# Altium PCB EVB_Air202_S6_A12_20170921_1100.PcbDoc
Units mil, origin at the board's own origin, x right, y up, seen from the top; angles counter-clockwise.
Board outline 964.57 x 1338.58 mil, 2 copper layers (Top, Bottom), stack 12.7 mil thick; 57 components, 47 nets, 194 pads, 152 vias.
Unrouted connection lines stored in the file: 113.
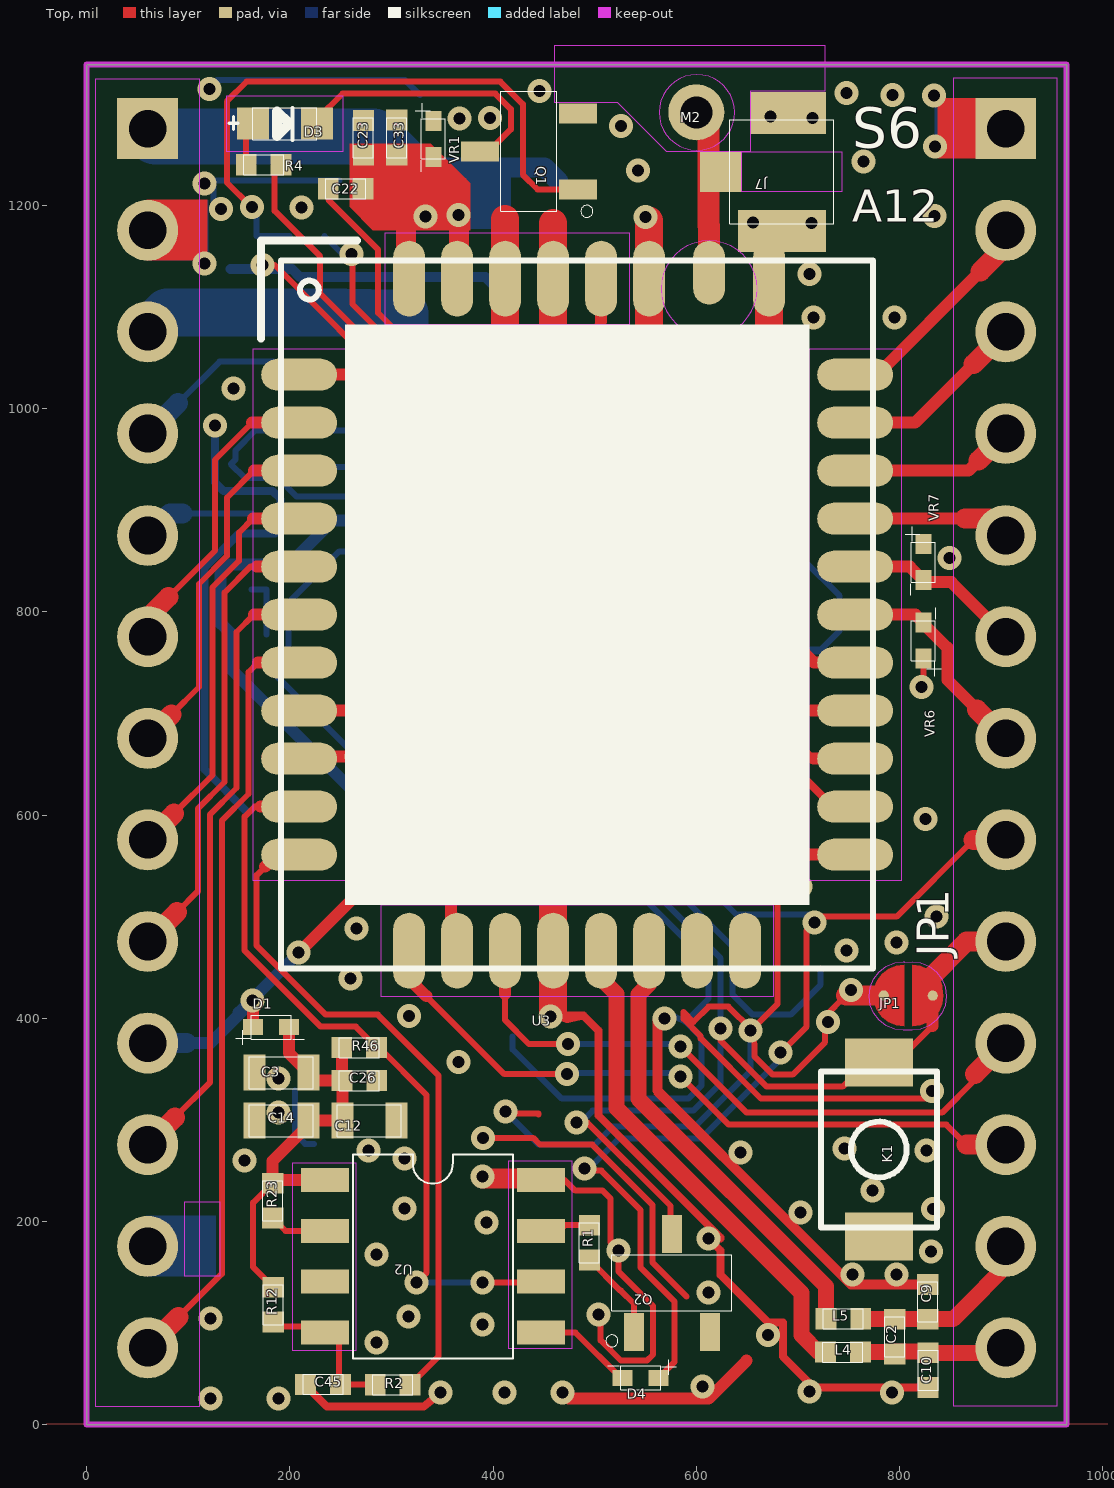
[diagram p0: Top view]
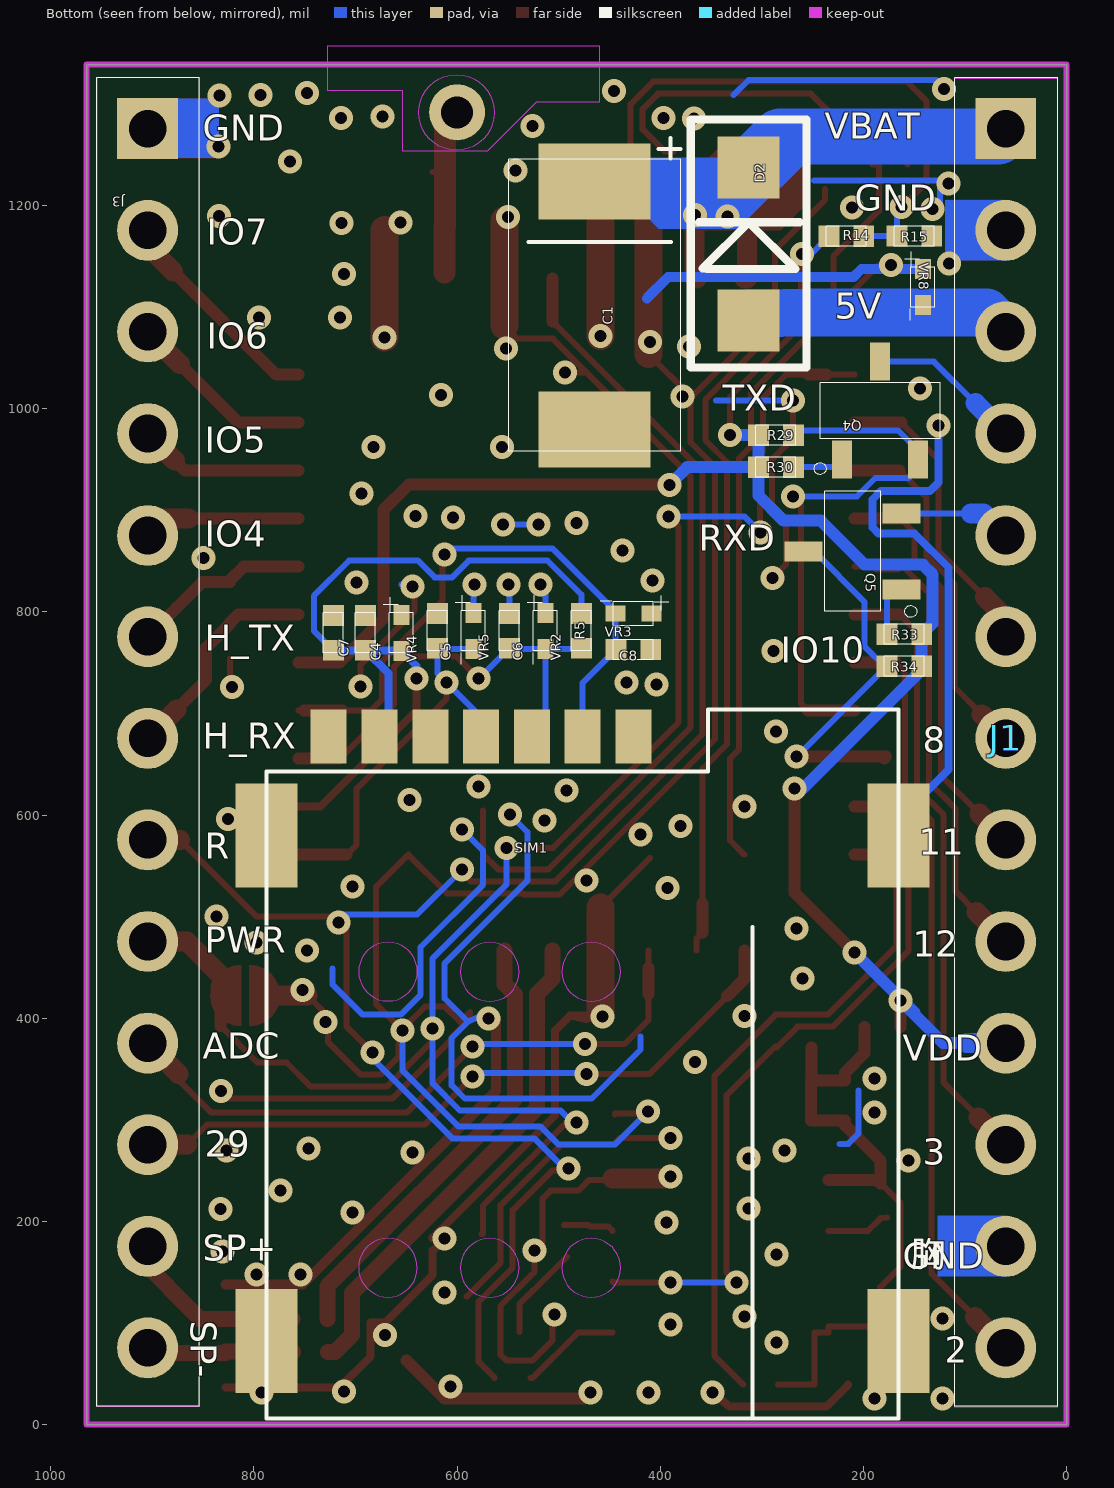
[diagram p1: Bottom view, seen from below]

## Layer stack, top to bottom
Solder Mask Top: solder mask 0.4, Solder Resist, Dk 3.5
Top: signal copper 1.35
Dielectric 1: dielectric 10, FR-4, Dk 4.3
Bottom: signal copper 1.35
Solder Mask Bottom: solder mask 0.4, Solder Resist, Dk 3.5

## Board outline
0,1338.58 964.57,1338.58 964.57,0 0,0

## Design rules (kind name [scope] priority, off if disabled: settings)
Clearance "Clearance - Default - DEFAULT- SMD" [IsVia vs IsSMTPin] p1: gap=5.91 ignorepadtopadclearanceinfootprint=FALSE
Clearance "Clearance - Default - DEFAULT - Via" [IsVia vs IsVia] p2: gap=5.91 ignorepadtopadclearanceinfootprint=FALSE
Clearance "Clearance - Default - DEFAULT - Net" [All] p3: gap=5.91 ignorepadtopadclearanceinfootprint=FALSE except(0: Arc-Hole Track-Hole SMDPad-Hole THPad-Hole Via-Hole Fill-Hole Poly-Hole Region-Hole Text-Hole; 10: Text-Text)
ComponentClearance "ComponentClearance - Default - DEFAULT" [All] p1: gap=6 collisioncheckmode=3 verticalgap=10 showdistances=FALSE
FanoutControl Fanout_LCC [IsLCC] p1: bgadir=Out bgaviamode=Centered fanoutstyle=Auto fanoutdirection=Alternating viagrid=1 // Fanout_LCC (Default Rule)
FanoutControl Fanout_BGA [IsBGA] p2: bgadir=Out bgaviamode=Centered fanoutstyle=Auto fanoutdirection=Alternating viagrid=1 // Fanout_BGA (Default Rule)
FanoutControl Fanout_Small [(CompPinCount < 5)] p3: bgadir=Out bgaviamode=Centered fanoutstyle=Auto fanoutdirection=OutThenIn viagrid=1 // Fanout_Small (Default Rule)
FanoutControl Fanout_SOIC [IsSOIC] p4: bgadir=Out bgaviamode=Centered fanoutstyle=Auto fanoutdirection=Alternating viagrid=1 // Fanout_SOIC (Default Rule)
HoleToHoleClearance "HoleToHoleClearance - Default - DEFAULT" [All] p1: gap=6 allowstackedmicrovias=TRUE
MaxMinImpedance "Default Impedance" [All] p1: minimum=50.00 maximum=150.0
ParallelSegment "Default Parallel Segment Same Layer" [All] p1: limit=1000 gap=200
ParallelSegment "Default Parallel Segment Adjasent" [All] p2: limit=1000 gap=200
PlaneConnect "Default PlaneConnect" [All] p1: planeconnectstyle=Relief reliefexpansion=20 reliefentries=0 reliefconductorwidth=15 reliefairgap=10
PolygonConnect "PolygonConnect - Default SMT" [IsSMTPin] p1: connectstyle=Direct reliefconductorwidth=11.81 reliefentries=4 polygonreliefangle="45 Angle" airgapwidth=10
PolygonConnect "PolygonConnect - Default Pad" [All] p2: connectstyle=Direct reliefconductorwidth=15 reliefentries=4 polygonreliefangle="45 Angle" airgapwidth=10
RoutingLayers "RoutingLayers - Default - DEFAULT" [All] p1: top layer_v5=TRUE bottom layer_v5=TRUE
RoutingPriority "RoutingPriority - Default - DEFAULT" [All] p1: routingpriority=3
RoutingTopology "Default Routing Topology" [All] p1: topology=Shortest
RoutingVias "RoutingVias - Default - DEFAULT" [All] p1: holewidth=11.81 width=23.62 viastyle="Through Hole" minholewidth=11.81 minwidth=23.62 maxholewidth=11.81 maxwidth=23.62
SMDToCorner "SMDToCorner - Default - DEFAULT" [All] p1: distance=59055
SolderMaskExpansion [All] p1: expansion=4
Width "Default Width" [All] p1: maxlimit=78.74 minlimit=5.91 preferedwidth=5.91
20 further rules are at their usual default settings.

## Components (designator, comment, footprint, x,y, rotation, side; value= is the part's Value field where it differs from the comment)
C1 "CASEN" CASEN 464.58,1101.65 r270 bottom
C2 "SC0402" SC0402 795.32,86.66 r90 top
C3 "SC0603" SC0603 191.58,346.63 r0 top
C4 "SC0402" SC0402 690.22,779.32 r270 bottom
C5 "SC0402" SC0402 619.35,781.29 r270 bottom
C6 "SC0402" SC0402 548.49,781.29 r270 bottom
C7 "SC0402" SC0402 721.72,779.32 r270 bottom
C8 "SC0402" SC0402 426.63,762.98 r0 bottom
C9 "SC0402" SC0402 827.77,121 r90 top
C10 "SC0402" SC0402 828.04,53.68 r270 top
C12 "SC0603" SC0603 278.2,299.39 r180 top
C14 "SC0603" SC0603 191.58,299.39 r0 top
C22 "SC0402" SC0402 254.91,1216.49 r180 top
C23 "SC0402" SC0402 272.3,1266.58 r90 top
C26 "SC0402" SC0402 268.35,338.76 r0 top
C33 "SC0402" SC0402 305.12,1266.91 r90 top
C45 "SC0402" SC0402 232.57,39.61 r0 top
D1 "ESD-TVS-UM5079" ESD-TVS-UM5079 181.4,391.44 r180 top
D2 "DO-214AC" DO-214AC 313,1237.48 r90 bottom
D3 "LED-0603" LED-0603 194.99,1280.54 r0 top
D4 "ESD-TVS-UM5079" ESD-TVS-UM5079 545.29,46.06 r0 top
J1 "DIP13X1-2.54" DIP13X1-2.54 60,1275.59 r270 bottom
J3 "DIP13X1-2.54" DIP13X1-2.54 904.57,1275.59 r270 bottom
J7 "RF-ANT-SOCKET-U.FL-R-SMT" RF-ANT-SOCKET-U.FL-R-SMT 684.25,1233.02 r270 top
JP1 "R60L08" R60L08 812.7,392.32 r0 top
K1 "KEY-2PIN" KEY-2PIN 779.64,270.87 r90 top
L4 "SL0402" SL0402 744.35,71.45 r180 top
L5 "SL0402" SL0402 744.76,104.24 r180 top
M2 "HOLE-0.9MM" HOLE-0.9MM 599.93,1291.77 r0 top
Q1 "SOT-23(MMBT3904)" SOT-23(MMBT3904) 435.16,1253.38 r0 top
Q2 "SOT-23(MMBT3904)" SOT-23(MMBT3904) 576.02,139.58 r270 top
Q4 "SOT-23(MMBT3904)" SOT-23(MMBT3904) 183.62,998.17 r270 bottom
Q5 "SOT-23(MMBT3904)" SOT-23(MMBT3904) 210.64,859.53 r180 bottom
R1 "SR0402" SR0402 494.86,179.23 r270 top
R2 "SR0402" SR0402 301.18,39.37 r180 top
R4 "SR0402" SR0402 174.06,1240.2 r0 top
R5 "SR0402" SR0402 477.62,781.29 r90 bottom
R12 "SR0402" SR0402 183.54,118.2 r270 top
R14 "SR0402" SR0402 216.93,1169.79 r180 bottom
R15 "SR0402" SR0402 149.97,1169.93 r0 bottom
R23 "SR0402" SR0402 183.07,220.47 r90 top
R29 "SR0402" SR0402 286.17,973.96 r0 bottom
R30 "SR0402" SR0402 286.17,942.47 r0 bottom
R33 "SR0402" SR0402 159.88,777.97 r180 bottom
R34 "SR0402" SR0402 159.88,746.48 r180 bottom
R46 "SR0402" SR0402 268.17,371.24 r0 top
SIM1 "5100106-X1101S-X-A" 5100106-X1101S-X-A 726.38,677.17 r180 bottom
U2 "EM78P153B-SOP8" EM78P153B-SOP8 340.62,165.81 r270 top
U3 "A6391_A11" A6391_A11 191.34,448.82 r0 top
VR1 "ESD-TVS-UM5079" ESD-TVS-UM5079 341.27,1265.66 r90 top
VR2 "ESD-TVS-UM5079" ESD-TVS-UM5079 513.06,781.29 r90 bottom
VR3 "ESD-TVS-UM5079" ESD-TVS-UM5079 426.63,798.41 r180 bottom
VR4 "ESD-TVS-UM5079" ESD-TVS-UM5079 654.79,779.32 r90 bottom
VR5 "ESD-TVS-UM5079" ESD-TVS-UM5079 583.92,781.29 r90 bottom
VR6 "ESD-TVS-UM5079" ESD-TVS-UM5079 823.5,771.72 r270 top
VR7 "ESD-TVS-UM5079" ESD-TVS-UM5079 823.49,848.9 r90 top
VR8 "ESD-TVS-UM5079" ESD-TVS-UM5079 141.68,1119.73 r90 bottom

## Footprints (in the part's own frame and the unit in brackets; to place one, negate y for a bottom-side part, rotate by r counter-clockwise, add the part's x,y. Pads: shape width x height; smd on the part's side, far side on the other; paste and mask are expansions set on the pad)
5100106-X1101S-X-A [mm]
  rect 0.9x1.35 smd: 1(0,0) 2(1.27,0) 3(2.54,0) 4(3.81,0) 5(5.08,0) 6(6.35,0) 7(7.62,0)
  rect 1.55x2.6 smd: 8(-1.55,-2.475) 9(14.25,-2.475) 10(-1.55,-15.105) 11(14.25,-15.105)
  Top keep-out region: 7.297,-13.277 7.241,-12.995 7.082,-12.757 6.844,-12.598 6.562,-12.542 6.562,-12.542 6.281,-12.598 6.043,-12.757 5.883,-12.995 5.827,-13.277 5.827,-13.277 5.883,-13.558 6.043,-13.796 6.281,-13.956 6.562,-14.012 6.562,-14.012 6.844,-13.956 7.082,-13.796 7.241,-13.558 7.297,-13.277
  Top keep-out region: 4.759,-13.279 4.703,-12.998 4.544,-12.76 4.306,-12.6 4.024,-12.544 4.024,-12.544 3.743,-12.6 3.505,-12.76 3.345,-12.998 3.289,-13.279 3.289,-13.279 3.345,-13.561 3.505,-13.799 3.743,-13.958 4.024,-14.014 4.024,-14.014 4.306,-13.958 4.544,-13.799 4.703,-13.561 4.759,-13.279
  Top keep-out region: 2.215,-13.274 2.159,-12.993 2,-12.754 1.762,-12.595 1.48,-12.539 1.48,-12.539 1.199,-12.595 0.961,-12.754 0.801,-12.993 0.745,-13.274 0.745,-13.274 0.801,-13.555 0.961,-13.794 1.199,-13.953 1.48,-14.009 1.48,-14.009 1.762,-13.953 2,-13.794 2.159,-13.555 2.215,-13.274
  Top keep-out region: 7.299,-5.875 7.243,-5.593 7.083,-5.355 6.845,-5.196 6.564,-5.14 6.564,-5.14 6.282,-5.196 6.044,-5.355 5.885,-5.593 5.829,-5.875 5.829,-5.875 5.885,-6.156 6.044,-6.394 6.282,-6.554 6.564,-6.61 6.564,-6.61 6.845,-6.554 7.083,-6.394 7.243,-6.156 7.299,-5.875
  Top keep-out region: 4.761,-5.877 4.705,-5.596 4.545,-5.358 4.307,-5.198 4.026,-5.142 4.026,-5.142 3.744,-5.198 3.506,-5.358 3.347,-5.596 3.291,-5.877 3.291,-5.877 3.347,-6.159 3.506,-6.397 3.744,-6.556 4.026,-6.612 4.026,-6.612 4.307,-6.556 4.545,-6.397 4.705,-6.159 4.761,-5.877
  Top keep-out region: 2.217,-5.872 2.161,-5.591 2.001,-5.352 1.763,-5.193 1.482,-5.137 1.482,-5.137 1.2,-5.193 0.962,-5.352 0.803,-5.591 0.747,-5.872 0.747,-5.872 0.803,-6.153 0.962,-6.392 1.2,-6.551 1.482,-6.607 1.482,-6.607 1.763,-6.551 2.001,-6.392 2.161,-6.153 2.217,-5.872
  silkscreen extent -1.55,-17.04 14.25,0.68
A6391_A11 [mm]
  oval 1.9x0.8 smd: 1(0.45,14.85) 2(0.45,13.65) 3(0.45,12.45) 4(0.45,11.25) 5(0.45,10.05) 6(0.45,8.85) 7(0.45,7.65) 8(0.45,6.45) 9(0.45,5.25) 10(0.45,4.05) 11(0.45,2.85) 20(14.35,2.85) 21(14.35,4.05) 22(14.35,5.25) 23(14.35,6.45) 24(14.35,7.65) 25(14.35,8.85) 26(14.35,10.05) 27(14.35,11.25) 28(14.35,12.45) 29(14.35,13.65) 30(14.35,14.85)
  oval 0.8x1.9 smd: 12(3.2,0.45) 13(4.4,0.45) 14(5.6,0.45) 15(6.8,0.45) 16(8,0.45) 17(9.2,0.45) 18(10.4,0.45) 19(11.6,0.45) 31(12.2,17.25) 33(9.2,17.25) 34(8,17.25) 35(6.8,17.25) 36(5.6,17.25) 37(4.4,17.25) 38(3.2,17.25)
  oval 0.8x1.6 smd: 32(10.7,17.4)
  rect 1.5x1.5 smd: 39(3.2,2.85) 40(11.6,2.85) 41(7.4,7.35)
  Top keep-out region: 2.6,18.4 8.7,18.4 8.7,16.1 2.6,16.1 2.6,18.4
  Top keep-out region: -0.7,15.5 1.6,15.5 1.6,2.2 -0.7,2.2 -0.7,15.5
  Top keep-out region: 2.5,1.6 12.3,1.6 12.3,-0.7 2.5,-0.7 2.5,1.6
  Top keep-out region: 13.2,15.5 15.5,15.5 15.5,2.2 13.2,2.2 13.2,15.5
  Top keep-out region: 11.9,17 11.809,17.459 11.549,17.849 11.159,18.109 10.7,18.2 10.7,18.2 10.241,18.109 9.851,17.849 9.591,17.459 9.5,17 9.5,17 9.591,16.541 9.851,16.151 10.241,15.891 10.7,15.8 10.7,15.8 11.159,15.891 11.549,16.151 11.809,16.541 11.9,17
  silkscreen extent -0.5,0 14.8,18.2
CASEN [mm]
  rect 1.9x2.8 smd: 1(-3.1,0) 2(3.1,0)
  silkscreen extent -4.18,-2.15 3.65,2.15
DIP13X1-2.54 [mil]
  rect 60x60 hole 37: 1(0,0)
  round 60 hole 37: 2(100,0) 3(200,0) 4(300,0) 5(400.39,0) 6(500,0) 7(600,0) 8(700,0) 9(800,0) 10(900,0) 11(1000,0) 12(1100,0) 13(1200,0)
  silkscreen extent -50,-50 1257,51
DO-214AC [mm]
  rrect0% 1.55x1.55 smd: 1(0,0) 2(-3.83,0)
  silkscreen extent -5,-1.45 1.2,1.45
EM78P153B-SOP8 [mm]
  rect 0.6x1.2 smd: 1(-1.905,-2.7) 2(-0.635,-2.7) 3(0.635,-2.7) 4(1.905,-2.7) 5(1.905,2.7) 6(0.635,2.7) 7(-0.635,2.7) 8(-1.905,2.7)
  silkscreen extent -2.55,-2 2.55,2
ESD-TVS-UM5079 [mm]
  rect 0.5x0.4 smd: 1(-0.45,0) 2(0.45,0)
  silkscreen extent -0.83,-0.3 0.89,0.45
HOLE-0.9MM [mm]
  round 1.4 hole 0.8: 1(0,0)
KEY-2PIN [mm]
  rect 1.2x1.7 smd: 1(-2.175,0) 2(2.175,0)
  silkscreen extent -1.95,-1.45 1.95,1.45
LED-0603 [mm]
  rect 0.8x0.8 smd: 1(-0.8,0) 2(0.8,0)
  Top keep-out region: -1.45,0.7 1.45,0.7 1.45,-0.7 -1.45,-0.7 -1.45,0.7
  silkscreen extent -1.39,-0.41 0.8,0.4
R60L08 [mil]
  round 10 smd: 1(-28.22,30.19) 2(20,30)
  Top region: -8.22,-0.07 -16.05,0.96 -23.35,3.98 -29.62,8.79 -34.42,15.06 -37.45,22.36 -38.48,30.19 -37.45,38.02 -34.42,45.32 -29.62,51.59 -23.35,56.39 -16.05,59.42 -8.22,60.45 -8.22,60.19 -8.22,0.19
  Top region: 0,60.26 7.83,59.23 15.13,56.2 21.4,51.4 26.2,45.13 29.23,37.83 30.26,30 29.23,22.17 26.2,14.87 21.4,8.6 15.13,3.8 7.83,0.77 0,-0.26 0,0 0,60
  Top keep-out region: -7.87,62.99 -0.02,63.22 8.24,62.13 16.39,58.76 23.38,53.4 28.74,46.41 32.11,38.26 33.26,29.53 32.11,20.79 28.74,12.65 23.38,5.66 16.39,0.29 8.24,-3.08 0.04,-4.16 0,-3.94 -7.86,-4.11 -8.86,-4.24 -17.6,-3.09 -25.74,0.28 -32.74,5.65 -38.1,12.64 -41.48,20.79 -42.63,29.53 -41.48,38.27 -38.1,46.41 -32.74,53.41 -25.74,58.77 -17.6,62.14 -8.86,63.3 -7.86,63.16 -7.87,62.99
RF-ANT-SOCKET-U.FL-R-SMT [mm]
  rect 1.05x1.9 smd: 1(-1.475,0.15)
  rect 1x1.05 smd: 2(0,-1.525)
  rect 1.05x2.2 smd: 3(1.475,0)
  Top keep-out region: -0.5,1.5 0.493,1.5 0.493,-1.003 -0.5,-1.003 -0.5,1.5
  silkscreen extent -1.3,-1.3 1.3,1.3
SC0402 [mm]
  rect 0.52x0.53 smd: 1(-0.435,0) 2(0.435,0)
  silkscreen extent -0.5,-0.25 0.5,0.25
SC0603 [mm]
  rect 0.551x0.899 smd: 1(-0.675,0) 2(0.675,0)
  silkscreen extent -0.8,-0.4 0.8,0.4
SL0402 [mm]
  rect 0.52x0.53 smd: 1(-0.435,0) 2(0.435,0)
  silkscreen extent -0.5,-0.25 0.5,0.25
SOT-23(MMBT3904) [mm]
  rect 0.95x0.5 smd: 1(1.225,-0.95) 2(1.225,0.95) 3(-1.225,0)
  silkscreen extent -0.7,-1.65 1.6,1.5
SR0402 [mm]
  rect 0.52x0.53 smd: 1(-0.435,0) 2(0.435,0)
  silkscreen extent -0.5,-0.25 0.5,0.25

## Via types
v1: diameter 23.62, hole 11.81, Top to Bottom, 152 vias

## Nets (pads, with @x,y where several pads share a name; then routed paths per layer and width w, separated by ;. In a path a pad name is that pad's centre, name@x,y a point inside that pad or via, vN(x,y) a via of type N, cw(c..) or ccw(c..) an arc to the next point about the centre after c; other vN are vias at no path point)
5V: J1.3 VR8.1 | length 279
  Bottom w5.91: VR8.1 145.52,1102.01 VR8.1@145.52,1094.63
  Bottom w47.24: J1.3 79.04,1094.63 145.52,1094.63 252.95,1094.63 306.11,1093.58 313,1093.58 313,1086.69
$$$3343: Q2.1 R1.2 | length 93.8
  Top w5.91: R1.2@491.61,165.35 R1.2 495.05,162.1 525.27,131.89 525.64,131.89 538.62,118.91 Q2.1
$$$5974: C45.2 R2.2 R12.2 U2.4 | length 162.2
  Top w5.91: R12.2 183.54,96.44 234.32,96.44 U2.4 248.38,90.81 248.38,39.61 C45.2 249.69,39.37 R2.2
$$$6421: D4.1 U2.5 | length 99.2
  Top w5.91: U2.5 480.85,90.81 525.6,46.06 D4.1
$$$8496: D3.1 R4.1 | length 46.9
  Top w5.91: R4.1 156.93,1280.54 D3.1
$$$8682: R23.1 U2.2 | length 62.7
  Top w5.91: R23.1@176.85,203.83 R23.1 195.61,190.81 U2.2
$$$8691: Q1.1 R14.2 R15.2 | length 624.7
  Top w5.91: v1(162.77,1198.32) 162.77,1199.7 160.78,1199.7 137.83,1222.65 137.83,1302.55 157.22,1321.93 407.1,1321.93 429.25,1299.77 429.25,1230.43 443.71,1215.98 Q1.1
  Bottom w5.91: v1(162.77,1198.32) v1@162.71,1198.91 ; R14.2 167.09,1169.79 167.09,1198.91 v1@162.71,1198.91 ; v1@162.71,1198.91 160.78,1198.91 162.69,1199.1 v1@162.71,1198.91
$$$8729: R1.1 U2.7 | length 50.2
  Top w5.91: U2.7 450.99,194.88 469,194.88 470.47,196.35 R1.1
$$$13186: C3.2 C12.2 C14.2 C26.1 D1.1 R12.1 R23.2 R46.1 U2.1 | length 446
  Top w5.91: R23.2 182.87,237.6 163.78,218.5 163.78,155.09 R12.1
  Top w11.81: R23.2 R23.2@183.07,240.81 ; D1.1 199.12,365.67 C3.2 218.16,338.58 251.23,338.58 C26.1 ; U2.1 R23.2@183.07,240.81 ; R46.1 251.05,338.76 C26.1 ; R23.2@183.07,240.81 183.07,259.65 218.16,294.73 C14.2 C12.2 251.62,338.76 C26.1
$$$15724: C2.1 C10.1 J3.13 L4.1 | length 151.4
  Top w15.75: L4.1 C2.1@795.32,71.45 ; C2.1 C2.1@795.32,71.45 ; J3.13 904.57,70.8 C10.1 828.04,71.92 795.32,71.92 C2.1@795.32,71.45
$$$15726: C2.2 C9.1 J3.12 L5.1 | length 192.8
  Top w15.75: L5.1 795.32,104.24 C2.2@795.32,103.87 ; C2.2 C2.2@795.32,103.87 ; J3.12 914.56,165.59 852.84,103.87 C9.1 C2.2@795.32,103.87
$$$17025: D3.2 Q1.3 | length 271.4
  Top w5.91: D3.2 226.48,1284.81 251.79,1310.12 402.2,1310.12 417.44,1294.88 417.44,1275.03 395.79,1253.38 Q1.3
$$$27435: J7.2 M2.1 U3.32 | length 180.4
  Top w5.91: J7.2@612.02,1233.02 J7.2
  Top w21.65: M2.1 610.73,1290.6 612.02,1289.32 612.02,1233.02 612.02,1180.12 612.29,1179.86 612.6,1149.61 U3.32
$$$30927: Q4.1 R30.1 | length 55.5
  Bottom w5.91: Q4.1 221.02,942.47 R30.1
$$$31323: Q5.1 R33.1 | length 58.7
  Bottom w5.91: Q5.1 177.01,822.12 R33.1
ADC: J3.10 U3.14 | length 630.7
  Top w5.91: 411.81,424.17 411.81,398.13 435.29,374.65 v1(473.91,374.65) ; U3.14@411.81,449.38 U3.14 ; v1(584.65,372.05) 649.61,307.09 842.03,307.09 874.33,339.38 874.33,345.35 ; J3.10@891.3,362.32 J3.10
  Top w11.81: 411.81,424.17 U3.14@411.81,449.38
  Top w19.68: 874.33,345.35 J3.10@891.3,362.32
  Bottom w5.91: v1(473.91,374.65) 582.04,374.65 v1(584.65,372.05)
GND: C1.2 C3.1 C4.1 C5.1 C6.1 C7.1 C8.1 C9.2 C10.2 C12.1 C14.1 C22.2 C23.2 C26.2 C33.2 C45.1 J1.2 J1.12 J3.1 J7.1 J7.3 JP1.1 K1.1 Q1.2 Q2.2 R15.1 SIM1.1 SIM1.8 SIM1.9 SIM1.10 SIM1.11 U2.8 U3.15 U3.31 U3.33 U3.35 U3.36 U3.39 U3.40 U3.41 VR1.2 VR2.2 VR3.2 VR4.2 VR5.2 VR6.2 VR7.2 VR8.2 | length 9139
  Top w5.91: v1(173.04,1141.48) 184.98,1141.48 310.67,1015.79 310.67,962.88 322.46,951.08 322.46,664.68 331.34,655.81 331.34,575.04 U3.39 ; C22.2 237.78,1205.68 286.93,1156.54 286.93,1094.25 v1@370.24,1010.94 ; v1(269.28,1007.93) 269.28,970.86 289.97,950.16 289.97,905.2 276.51,891.73 276.51,846.51 v1(289.59,833.43) ; v1(378.37,1011.87) v1@370.24,1010.94 ; v1@389.76,242.45 v1(389.76,244.09) ; v1(390.13,282.42) 439.34,282.42 446.17,275.59 497.66,275.59 557.09,216.16 557.09,159.45 590.55,125.98 ; 409.95,558.03 459.06,508.92 ; 411.81,1053.91 370.24,1012.34 v1@370.24,1010.94 ; v1(412.3,308.08) 412.3,306.37 444.5,306.37 444.5,305.57 ; U2.8@446.92,242.45 U2.8 470.47,240.81 480.96,230.31 507.87,230.31 515.75,222.44 515.75,179.13 v1(523.62,171.26) 523.62,150.59 527.07,147.15 557.32,116.91 557.32,68.98 551.33,62.99 525.91,62.99 505.91,83 505.91,106.3 v1(503.94,108.27) ; v1(493.85,1035.85) 472.81,1035.85 ; v1(549.86,1188.79) v1@553.54,1185.1 ; 553.54,1081.69 540.72,1068.87 505.82,1068.87 472.81,1035.85 ; 574.74,604.54 574.74,561.62 559.71,546.59 510.1,546.59 370.16,686.54 370.16,933.15 425.22,988.22 425.22,988.27 472.81,1035.85 ; v1(643.7,824.8) 641.73,824.8 641.73,801.18 694.88,748.03 v1(694.88,726.38) ; v1@747.26,422.51 726.86,402.11 726.86,376.47 694.88,344.49 675.2,344.49 657.48,362.2 657.48,374.02 v1(653.54,387.8) ; v1(821.73,726.19) 823.11,726.19 823.11,727.29 823.5,727.68 VR6.2 ; v1(832.2,328.34) 834.15,320.87 663.68,320.87 604.33,380.22 604.33,382.53 587.48,399.38 587.48,406.02 597.15,396.35 612.22,411.42 631.59,411.42 v1@654.38,388.63 ; v1@370.24,1010.94 370.24,966.76 346.18,942.71 346.18,674.7 499.22,521.65 534.13,521.65 535.43,522.95 609.96,522.95 U3.40 680.01,529.04 680.01,414.26 v1@654.38,388.63 ; v1(653.54,387.8) 657.48,385.53 v1@654.38,388.63 ; v1(653.54,387.8) v1@654.38,388.63
  Top w7.87: C45.1 215.09,39.61 215.09,39.06 236.43,17.72 331.58,17.72 v1(348.43,31.5) ; v1(456.69,401.57) 455.36,403.91 457.81,405.3 458.11,405.18 473.04,399.32 488.74,402.89 ; v1@459.06,408.29 464.46,402.89 488.74,402.89 ; C10.2 715.63,36.55 685.24,66.94 685.24,100.39 671.03,100.39 624.02,147.4 624.02,171.26 v1(612.2,183.07) 624.02,183.07 624.02,184.03 618.59,189.46 503.49,304.56 503.49,388.14 488.74,402.89
  Top w9.84: v1(568.9,399.61) 565.98,402.53 561.56,398.11 561.56,328.74 692.2,198.1 752.18,138.13 C9.2
  Top w11.81: v1(468.5,31.5) 474.41,25.59 612.2,25.59 649.61,62.99
  Top w19.68: v1@389.76,242.45 U2.8@446.92,242.45 ; v1(752.11,427.66) 747.26,422.51 JP1.1
  Top w27.56: 411.81,1053.91 411.81,1186.96 ; v1@459.06,408.29 459.06,508.92 ; v1(459.06,1071.5) 459.06,1182.68 ; 553.54,1081.69 v1@553.54,1185.1 ; v1(671.65,1070) U3.31 J7.3@671.65,1175.93
  Bottom w5.91: v1(121.01,1314.66) 120.29,1315.38 128.39,1323.48 313.25,1323.48 327.8,1308.93 ; v1@124.63,1199.45 124.63,1224.43 248.84,1224.43 ; 205.03,328.77 205.03,286.44 214.99,276.48 223.77,276.48 ; v1(269.28,1007.93) 345.16,1007.93 ; v1(412.3,308.08) 444.79,275.59 500,275.59 517.72,293.31 598.43,293.31 653.54,348.43 v1(653.54,387.8) ; 419.29,381.89 419.29,369.26 467.69,320.87 592.22,320.87 605.31,333.96 605.31,380.61 589.3,396.62 ; VR2.2 513.06,823.56 511.81,824.8 511.81,826.77 513.78,828.74 v1(517.72,826.77) ; v1(520.05,886.01) v1(555.03,886.01) ; v1(548.1,600.56) 530.93,583.39 530.93,535.46 612.2,454.19 612.2,419.52 589.3,396.62 ; C6.1 548.49,826.05 v1(549.21,826.77) ; v1(568.9,399.61) 571.49,405.07 589.3,396.62 ; v1(582.68,826.77) 582.68,824.8 583.92,823.56 VR5.2 ; v1(595.35,585.95) 574.42,565.02 574.42,531.62 635.83,470.22 635.83,423.23 655.51,403.54 692.91,403.54 722.44,433.07 722.44,448.82 ; v1(643.7,824.8) 643.5,825.39 647.64,826.77 v1@654.68,826.77
  Bottom w7.87: v1(126.34,983.59) 126.34,927.35 134.69,919 182.8,919 190.96,910.85 190.96,883.01 185.18,877.23 150,877.23 116.15,843.39 116.15,644.85 SIM1.9@158.35,602.65
  Bottom w9.84: VR8.2 202.06,1137.44 210.03,1129.48 392.53,1129.48 413.35,1108.66
  other v1: 122.05,25.59 188.98,25.59 411.42,31.5 711.34,32.69 792.61,31.84 606.3,37.4 285.43,80.71 670.79,88.23 389.76,98.43 122.05,104.33 316.93,106.3 612.2,129.92 753.94,147.64 797.24,147.64 285.43,167.32 831.13,170.66 393.7,198.82 702.76,208.66 312.99,212.6 832.82,212.57 773.62,230.31 155.51,259.84 312.99,261.81 643.7,267.72 277.56,269.68 826.77,269.68 746.06,271.65 188.98,307.09 188.98,340.55 365.71,357.09 729.59,396.49 317.21,402.46 259.84,438.98 747.66,466.58 797.24,474.41 265.75,488.19 836.61,500 393.02,528.39 702.76,529.53 472.44,535.43 419.29,580.71 380.16,589.27 513.78,594.49 825.43,595.99 316.93,608.27 647.02,614.84 492.13,624.02 578.74,627.95 286.26,682.31 403.54,728.35 433.07,730.31 288.36,761.44 698.82,828.74 407.48,830.71 849.4,853.16 437.01,860.24 482.31,887.31 603.89,893.14 640.91,894.65 694.06,916.32 555.77,962.23 682.28,962.23 615.89,1013.61 144.31,1019.93 552,1059.33 371.93,1061.25 409.96,1065.85 794.95,1089.54 715.34,1089.93 711.58,1132.8 115.93,1142.93 655.97,1183.11 713.57,1182.83 834.38,1189.45 132.1,1196.6 211.26,1198.08 116.16,1221.6 542.47,1234.38 764.58,1243.29 834.74,1258.23 525.67,1278.45 367,1285.52 396.77,1286.32 714.41,1286.06 673.22,1287.73 793.32,1308.65 834.02,1308.29 747.93,1310.8 445.54,1312.77
M_HOST_RX: J3.7 U3.25 VR6.1 | length 217.9
  Top w11.81: U3.25 815.69,797.24 VR6.1 823.5,788.43 847.1,764.82 847.1,733.06 876.13,704.03
  Top w19.68: 876.13,704.03 J3.7
M_HOST_TX: J3.6 U3.26 VR7.1 | length 206.6
  Top w11.81: U3.26 810.19,844.49 VR7.1 823.49,829.21 850.95,829.21 875.98,804.17 890.26,789.9 J3.6@902.24,777.91 ; J3.6@890.26,777.91 J3.6@902.24,777.91 ; J3.6@902.24,777.91 J3.6 904.57,777.91 J3.6@902.24,777.91
  Top w19.68: J3.6@890.26,777.91 J3.6@890.26,789.9
M_UART1_RXD: Q5.3 R34.1 U3.9 | length 404
  Top w5.91: U3.9@179.19,655.51 U3.9
  Top w11.81: U3.9@177.92,657.48 U3.9@181.15,657.48 ; U3.9@179.19,655.51 U3.9@181.15,657.48 ; v1(265.75,657.48) 263.78,655.51 261.81,657.48 U3.9@181.15,657.48
  Bottom w5.91: Q5.3 248.67,859.53 198.82,809.67 198.82,765.76 178.37,745.31 178.37,746.48 R34.1 265.88,657.61 v1(265.75,657.48)
M_UART1_TXD: Q4.2 R29.1 U3.8 | length 553.9
  Top w5.91: 254.45,702.76 261.64,709.95 261.64,906.1 v1(269.31,913.76)
  Top w11.81: U3.8 254.45,702.76
  Bottom w5.91: R29.1 269.04,978.56 165.97,978.56 146.22,958.8 Q4.2 141.79,945.51 155.41,931.89 188.24,931.89 206.37,913.76 v1(269.31,913.76)
NET_LED: R14.1 U3.13 | length 784.4
  Top w5.91: v1(260.69,1152.51) 261.57,1151.63 261.57,1102.86 355.77,1008.66 355.77,969 334.37,947.6 334.37,669.8 358.43,645.75 358.43,512.78 ; U3.13@358.43,484.57 364.57,478.43 U3.13
  Top w11.81: U3.13@358.43,484.57 358.43,512.78
  Bottom w5.91: R14.1 256.01,1147.83 v1(260.69,1152.51)
PWRKEY: J3.9 JP1.2 K1.2 Q2.3 U3.1 | length 1738.4
  Top w5.91: U3.1 U3.1@236.63,1033.46 ; 254.11,1033.46 276.29,1033.46 298.82,1010.94 298.82,958.02 301.79,955.06 301.79,878.56 v1(301.18,877.95) ; v1(391.73,893.7) 381.97,883.94 381.97,691.43 505.68,567.71 v1(551.6,567.71) ; v1(482.28,297.24) 492.71,297.24 574.59,215.37 574.59,187.81 Q2.3 ; v1(624.02,389.76) 624.02,377.95 669.29,332.68 744.09,332.68 767.92,356.5 K1.2 796.65,356.5 832.7,392.55 ; J3.9@889.16,475.59 J3.9
  Top w11.81: U3.1@236.63,1033.46 254.11,1033.46 ; 832.7,392.55 JP1.2
  Top w19.68: JP1.2 832.7,430.83 826.95,436.57 865.97,475.59 J3.9@889.16,475.59
  Bottom w5.91: v1(301.18,877.95) 316.93,893.7 v1(391.73,893.7) ; v1(482.28,297.24) 484.25,295.28 498.03,309.06 597.12,309.06 624.02,335.96 v1(624.02,389.76) 624.02,459.08 551.6,531.5 v1(551.6,567.71)
RESET: D4.2 J3.8 U3.34 | length 1827.3
  Top w5.91: v1(490.16,251.97) 492.13,250 506.55,250 545.28,211.27 545.28,154.56 578.74,121.09 578.74,61.8 D4.2 ; 506.3,1086.05 358.27,938.02 358.27,679.88 503.38,534.77 586.71,534.77 595.09,543.16 v1(595.09,546.43) ; v1(683.07,366.14) 708.66,391.73 708.66,486.22 v1(716.54,494.09) 722.44,500 797.24,500 872.83,575.59
  Top w11.81: 506.3,1086.05 U3.34
  Top w19.68: 872.83,575.59 J3.8
  Bottom w5.91: v1(490.16,251.97) 492.13,250 523.62,281.5 604.33,281.5 683.07,360.24 v1(683.07,366.14) ; v1(595.09,546.43) 639.55,501.97 716.54,501.97 v1(716.54,494.09)
SIM0CLK: C8.2 SIM1.6 U3.23 VR3.1 | length 589.2
  Top w5.91: v1(612.2,856.3) 614.17,856.3 614.17,811.02 673.73,751.46 673.73,714.06 685.04,702.76 713.28,702.76 ; U3.23@750.92,702.76 U3.23
  Top w11.81: 713.28,702.76 U3.23@750.92,702.76
  Bottom w5.91: SIM1.6 476.38,730.16 443.75,762.78 C8.2 444.34,763.57 VR3.1 444.34,800.64 505.96,862.26 606.25,862.26 v1(612.2,856.3)
SIM0DA: C6.2 R5.1 SIM1.5 U3.22 VR2.1 | length 456.3
  Top w5.91: v1(578.74,734.25) 600.39,755.91 652.08,755.91 661.92,746.06 661.92,709.17 715.58,655.51
  Top w11.81: 715.58,655.51 U3.22
  Bottom w5.91: R5.1 477.62,763.57 VR2.1 ; SIM1.5 513.06,690.49 VR2.1 ; v1(578.74,734.25) 548.64,764.16 C6.2 548.49,763.57 VR2.1
SIM0RST: C5.2 SIM1.4 U3.20 VR5.1 | length 397.9
  Top w5.91: v1(610.24,730.31) 610.24,714.57 698.82,625.98 698.82,570.87 708.66,561.02
  Top w11.81: 708.66,561.02 U3.20
  Bottom w5.91: SIM1.4 576.38,696.46 v1(610.24,730.31) 619.35,739.43 C5.2@619.35,763.57 ; VR5.1 C5.2@619.35,763.57 ; C5.2 C5.2@619.35,763.57
SPI1_CLK/GPIO_8: J1.7 U3.3 | length 351.2
  Top w5.91: 83.64,699.23 110.46,726.05 110.46,827.51 138.06,855.1 138.06,912.56 164.48,938.98
  Top w11.81: 164.48,938.98 U3.3
  Top w19.68: J1.7 83.64,699.23
SPI1_CS/GPIO_10: J1.6 U3.2 | length 299.5
  Top w5.91: J1.6 J1.6@60,781.51 ; 80.59,814.67 126.21,860.29 126.21,949.75 162.68,986.22
  Top w11.81: 162.68,986.22 U3.2
  Top w19.68: J1.6@60,781.51 60,794.08 80.59,814.67
SPI1_DI/GPIO_12: J1.9 U3.5 | length 458.7
  Top w5.91: J1.9 J1.9@65.55,481.14 ; 88.87,504.46 109.36,524.95 109.36,606.3 135.62,632.56 135.62,819.02 161.09,844.49 166.93,844.49 ; U3.5@186.63,844.49 U3.5
  Top w11.81: 166.93,844.49 U3.5@186.63,844.49
  Top w19.68: J1.9@65.55,481.14 88.87,504.46
SPI1_DO/GPIO_11: J1.8 U3.4 | length 404.6
  Top w5.91: 85.84,601.43 123.81,639.4 123.81,824.15 149.87,850.21 149.87,878.11 163.49,891.73
  Top w11.81: 163.49,891.73 U3.4
  Top w19.68: J1.8 85.84,601.43
SPK+: L4.2 U3.16 | length 490.7
  Top w15.75: U3.16 506.3,438.98 521.21,424.07 521.21,311.9 703.62,129.49 703.62,88.1 720.27,71.45 L4.2
SPK-: L5.2 U3.17 | length 443.3
  Top w15.75: U3.17 553.54,433.91 542.86,423.23 542.86,320.87 727.63,136.09 L5.2
UART1_CTS/GPIO3: J1.11 U3.6 | length 609.5
  Top w5.91: 86.86,302.45 121.17,336.76 121.17,600.39 147.43,626.65 147.43,780.2 164.48,797.24
  Top w11.81: 164.48,797.24 U3.6
  Top w19.68: J1.11 86.86,302.45
UART1_DCD/WD: R46.2 U2.6 U3.10 | length 740.4
  Top w5.91: 171.26,608.27 165.35,608.27 155.51,598.43 155.51,466.54 230.31,391.73 264.81,391.73 R46.2 286.65,371.24 286.65,372.4 334.65,324.4 334.65,149.61 v1(324.8,139.76) ; v1(389.76,139.76) 445.88,139.76 U2.6
  Top w11.81: 171.26,608.27 U3.10
  Bottom w5.91: v1(324.8,139.76) v1(389.76,139.76)
UART1_DTR/GPIO29: J3.11 U3.12 | length 683.1
  Top w5.91: 334.27,421.75 410.98,345.03 v1(472.76,345.03) ; v1(584.65,342.52) 631.89,295.28 846.14,295.28 865.83,275.59 ; J3.11@893.25,275.59 J3.11
  Top w11.81: U3.12 317.32,438.69 334.27,421.75
  Top w19.68: 865.83,275.59 J3.11@893.25,275.59
  Bottom w5.91: v1(472.76,345.03) 476.96,345.96 581.21,345.96 v1(584.65,342.52)
UART1_RI/RWD: R2.1 U3.11 | length 667.8
  Top w5.91: 175.59,549.21 167.32,540.94 167.32,471.43 235.13,403.62 286.46,403.62 346.46,343.63 346.46,67.52 R2.1 R2.1@318.31,39.57
  Top w11.81: 175.59,549.21 187.4,561.02 U3.11
UART1_RTS/GPIO2: J1.13 U3.7 | length 759.9
  Top w5.91: 90.2,105.79 132.98,148.57 132.98,594.49 159.24,620.75 159.24,740.77 168.46,750
  Top w11.81: 168.46,750 U3.7
  Top w19.68: J1.13 90.2,105.79
UART1_RXD: J1.5 Q5.2 | length 111.4
  Bottom w5.91: J1.5 J1.5@63.24,878.44 ; 94.2,896.93 Q5.2
  Bottom w19.68: J1.5@63.24,878.44 81.73,896.93 94.2,896.93
UART1_TXD: J1.4 Q4.3 | length 152.9
  Bottom w5.91: J1.4 J1.4@66.35,981.94 ; 90.01,1005.6 130.8,1046.39 Q4.3
  Bottom w19.68: J1.4@66.35,981.94 90.01,1005.6
UART2_CTS/GPIO_7/I2C3_SDA: J3.2 U3.30 | length 216.2
  Top w11.81: U3.30 777.95,1033.46 879.54,1135.05
  Top w19.68: 879.54,1135.05 904.57,1160.08 J3.2
UART2_RTS/GPIO_6/I2C3_SCL: J3.3 U3.29 | length 185.3
  Top w11.81: U3.29 815.2,986.22 872.98,1044
  Top w19.68: 872.98,1044 J3.3
UART2_RXD/GPIO_4/LPG: J3.5 U3.27 | length 155.1
  Top w11.81: U3.27 864.27,891.73
  Top w19.68: 864.27,891.73 888.03,891.73 J3.5
UART2_TXD/GPIO_5/PWM: J3.4 U3.28 | length 163.4
  Top w11.81: U3.28 867.95,938.98 877.82,948.85
  Top w19.68: 877.82,948.85 J3.4
VBAT: C1.1 C22.1 C23.1 C33.1 J1.1 U3.37 U3.38 VR1.1 | length 1059.1
  Top w5.91: 302.05,1219.48 314.44,1219.48 333.78,1219.48 ; v1(333.67,1189.18) 333.78,1192.49 333.78,1219.48 ; v1(365.85,1190.5) 364.57,1190.55 364.57,1217.78 366.27,1219.48 ; 366.6,1221.19 366.6,1219.81 ; 333.78,1219.48 366.27,1219.48 ; 366.27,1219.48 366.6,1219.48 366.6,1219.81 ; 366.27,1219.48 366.6,1219.81
  Top w19.68: 314.44,1219.48 314.44,1127.95 U3.38 ; U3.37 366.6,1127.95 366.6,1219.48
  Bottom w5.91: 313,1237.48 333.78,1237.48 333.78,1192.49 v1(333.67,1189.18)
  Bottom w19.68: 333.78,1237.48 450.8,1237.48 C1.1
  Bottom w47.24: J1.1 68.57,1267.02 265.06,1267.02 294.61,1237.48 313,1237.48
  Bottom w55.12: J1.1 67.47,1268.12 282.36,1268.12 313,1237.48
VDDIO: D1.2 J1.10 R4.2 R29.2 R30.2 R33.2 R34.2 U3.24 | length 1910.1
  Top w5.91: R4.2 184.9,1240.2 184.9,1194.78 229.74,1149.93 229.74,1113.42 331.4,1011.76 v1(331.4,973.92)
  Top w11.81: v1(163.39,417.32) 163.68,417.32 D1.2 ; v1(208.66,464.57) 267.72,523.62 v1(267.72,625.98) ; v1(391.19,924.95) 396.85,925.33 647.57,925.33 672.53,900.37 672.53,793.31 715.84,750 U3.24
  Bottom w5.91: R34.2@142.76,744.52 R34.2
  Bottom w11.81: J1.10 J1.10@66.93,375.59 ; 98.43,375.59 121.65,375.59 149.61,403.54 ; R34.2@142.76,744.52 142.76,743.07 259.84,625.98 v1(267.72,625.98) ; R34.2 R33.2 131.9,788.83 131.9,836.86 141.56,846.52 198.82,846.52 242.06,889.76 278.71,889.76 303.29,914.34 R30.2 ; v1(163.39,417.32) 149.61,403.54 ; v1(208.66,464.57) 149.61,405.51 149.61,403.54 ; v1@331.4,973.96 R29.2 R30.2 ; v1(391.19,924.95) 373.67,942.47 R30.2
  Bottom w19.68: J1.10@66.93,375.59 98.43,375.59
VSIM0: C4.2 C7.2 R5.2 SIM1.2 U3.21 VR4.1 | length 777.1
  Top w7.87: v1(639.76,734.25) 639.76,703.15 734.65,608.27 U3.21
  Bottom w5.91: R5.2 477.62,816.93 511.09,850.39 588.58,850.39 604.95,834.03 622.05,834.03 638.41,850.39 706.4,850.39 741.01,815.78 741.01,781.29 721.91,762.19 C7.2
  Bottom w7.87: R5.2 R5.2@477.82,798.41 ; v1(639.76,734.25) 639.76,746.58 VR4.1 654.79,762.16 C4.2@690.18,762.16 ; SIM1.2 667.32,677.17 667.32,739.3 C4.2@690.18,762.16 ; C7.2 C4.2 C4.2@690.18,762.16
pads on no net: D2.1 D2.2 SIM1.3 SIM1.7 U2.3 U3.18 U3.19

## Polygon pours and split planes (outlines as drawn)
GND on Top "Top-GND" (solid, remove dead copper, pour order 0): -136.04,1436.97 1013.31,1436.97 1013.31,0.41 -136.04,0.41
GND on Bottom "Bottom-GND" (solid, remove dead copper, pour order 2): -227.34,1504.24 1062.94,1504.24 1062.94,-141.33 -227.34,-141.33

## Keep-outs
Top:
  region: 202.76,257.87 264.63,257.87 264.63,72.83 202.76,72.83 202.76,257.87
  region: 415.35,259.84 477.23,259.84 477.23,74.8 415.35,74.8 415.35,259.84
  region: 96.61,219.32 130.71,219.32 130.71,145.97 96.61,145.97 96.61,219.32
Keep-Out Layer:
  region: 460.26,1357.38 460.26,1301.86 522.2,1301.86 570.56,1253.5 653.43,1253.5 653.43,1312.73 727.14,1312.73 727.14,1357.38 460.26,1357.38
  region: 9.03,1325.01 110.6,1325.01 110.6,17.48 9.03,17.48 9.03,1325.01
  region: 853.29,1325.97 954.58,1325.97 954.58,18.03 853.29,18.03 853.29,1325.97
  region: 637.74,1291.67 ccw(c600.56,1291.67) 600.56,1328.85 ccw(c600.56,1291.67) 563.38,1291.67 ccw(c600.56,1291.67) 600.56,1254.49 ccw(c600.56,1291.67)
  lines w5.91: 0,0 964.57,0 964.57,1338.58 0,1338.58 0,0

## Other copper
Top:
  region net GND: 59.32,1205.56 118.4,1205.56 118.4,1146.15 59.32,1146.15 59.32,1205.56
  region net VBAT: 258.77,1260.91 338.61,1260.91 377.68,1221.84 377.68,1175.87 281.56,1175.87 258.77,1198.66 258.77,1260.91
  region net GND: 837.87,1305.5 895.12,1305.5 895.12,1246.29 837.87,1246.29 837.87,1305.5
Bottom:
  region net GND: 834.7,1305.21 882.85,1305.21 882.85,1246.93 834.7,1246.93 834.7,1305.21
  region net VBAT: 290.5,1233.25 417.51,1233.25 417.51,1193.36 401.48,1177.34 324.28,1177.34 323.91,1176.97 290.5,1210.38 290.5,1233.25
  region net GND: 58.66,1205.35 119.72,1205.35 119.72,1146.15 58.66,1146.15 58.66,1205.35
  region net GND: 58.49,205.5 127.18,205.5 127.18,146.1 58.49,146.1 58.49,205.5

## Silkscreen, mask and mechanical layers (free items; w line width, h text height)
Silkscreen Top:
  text "S6" at 753.43,1256.97 h39.37
  text "A12" at 753.43,1184.08 h31.5
  text "JP1" at 848.43,460.63 h31.5 r90
Silkscreen Bottom:
  text "VBAT" at 238.19,1265.75 h25.59
  text "GND" at 850.39,1263.78 h25.59
  text "GND" at 208.66,1194.88 h25.59
  text "IO7" at 846.46,1161.42 h25.59
  text "5V" at 228.35,1088.58 h25.59
  text "IO6" at 846.46,1059.06 h25.59
  text "TXD" at 338.58,998.03 h25.59
  text "IO5" at 848.43,956.69 h25.59
  text "IO4" at 848.43,864.17 h25.59
  text "RXD" at 362.2,860.24 h25.59
  text "H_TX" at 848.43,761.81 h25.59
  text "IO10" at 281.5,750 h25.59
  text "H_RX" at 850.39,665.35 h25.59
  text "8" at 141.73,661.42 h25.59
  text "11" at 145.67,561.02 h25.59
  text "R" at 848.43,557.09 h25.59
  text "PWR" at 848.43,464.57 h25.59
  text "12" at 151.57,460.63 h25.59
  text "ADC" at 850.39,360.24 h25.59
  text "VDD" at 161.42,358.27 h25.59
  text "29" at 848.43,263.78 h25.59
  text "3" at 141.73,255.91 h25.59
  text "SP+" at 850.39,161.42 h25.59
  text "胸" at 153.54,155.51 h25.59
  text "GND" at 161.42,153.54 h25.59
  text "SP-" at 862.2,102.36 h25.59 r90
  text "2" at 120.08,61.02 h25.59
